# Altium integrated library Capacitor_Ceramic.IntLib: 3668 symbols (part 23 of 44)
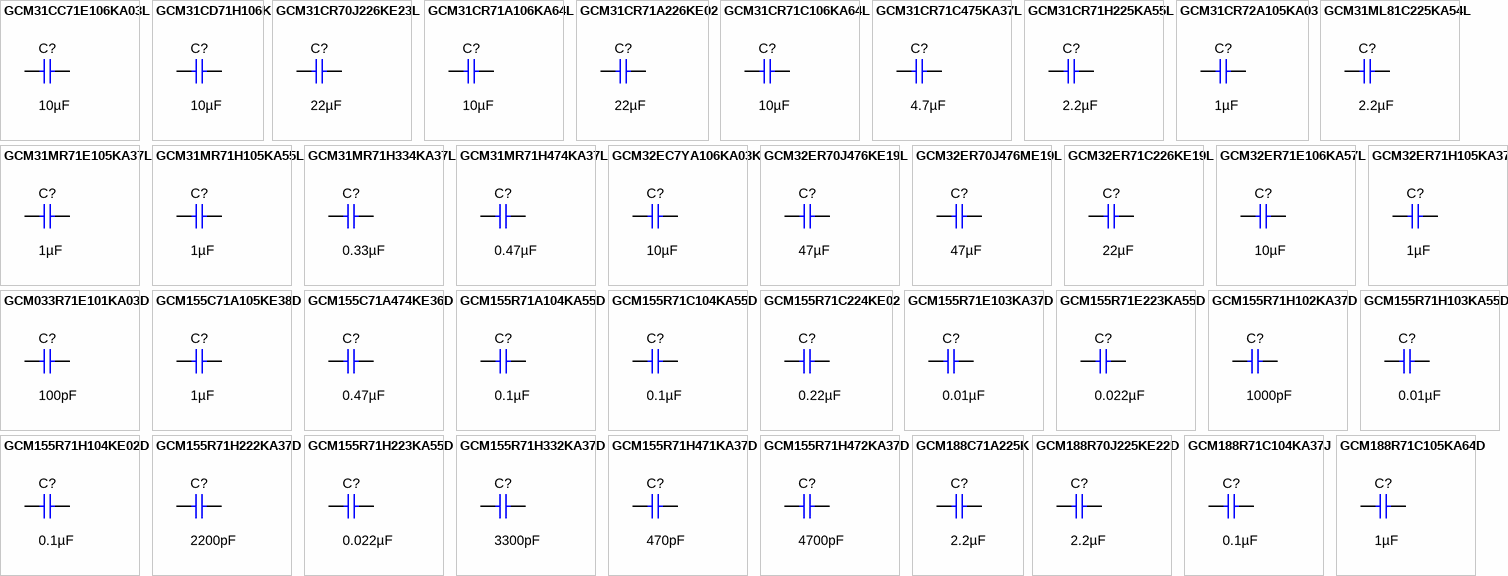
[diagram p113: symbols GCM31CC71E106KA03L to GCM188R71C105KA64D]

## GCM32ER70J476KE19L
designator C?  ValueDisplayed: 47µF  (hidden comment: GCM32ER70J476KE19L)
CAP, CERM, 47 µF, 6.3 V,+/- 10%, X7R, AEC-Q200 Grade 1, 1210; Manufacturer: MuRata; Polarized: N; CompType: Capacitor; Value: 47uF; U/M: EA; Cap_F: 0.000047; Tolerance_%: 10; VDC_V: 6.3; Value2: 6.3V; TaMin_C: -55; TaMax_C: 125; Cap_Case: 1210; SizeArea_mm2: 8; SizeAreaWB_mm2: 14.7; SizeX_mm: 3.2; SizeY_mm: 2.5; SizeZ_mm: 2.7; AEC Category: Q200; AEC Qualified: Y; AEC Grade: 1; Green_Lifecycle: Active; Green_REACh: Passed
signal-integrity model Cap
simulation model Cap
footprint 1210_270
footprint 1210_270M
footprint 1210_270L
pins: 1, 2

## GCM32ER70J476ME19L
designator C?  ValueDisplayed: 47µF  (hidden comment: GCM32ER70J476ME19L)
CAP, CERM, 47 µF, 6.3 V,+/- 20%, X7R, 1210; Manufacturer: MuRata; Polarized: N; CompType: Capacitor; Value: 47uF; U/M: EA; Cap_F: 0.000047; Tolerance_%: 20; VDC_V: 6.3; Value2: 6.3V; TaMin_C: -55; TaMax_C: 125; Cap_Case: 1210; SizeArea_mm2: 8; SizeAreaWB_mm2: 14.7; SizeX_mm: 3.2; SizeY_mm: 2.5; SizeZ_mm: 2.8; AEC Category: Q200; Green_Lifecycle: Active; Green_REACh: Passed
signal-integrity model Cap
simulation model Cap
footprint 1210_280
pins: 1, 2

## GCM32ER71C226KE19L
designator C?  ValueDisplayed: 22µF  (hidden comment: GCM32ER71C226KE19L)
CAP, CERM, 22 µF, 16 V,+/- 10%, X7R, 1210; Manufacturer: MuRata; Polarized: N; CompType: Capacitor; Value: 22uF; U/M: EA; Cap_F: 0.000022; Tolerance_%: 10; VDC_V: 16; Value2: 16V; TaMin_C: -55; TaMax_C: 125; Cap_Case: 1210; SizeArea_mm2: 8; SizeAreaWB_mm2: 14.7; SizeX_mm: 3.2; SizeY_mm: 2.5; SizeZ_mm: 2.8; AEC Category: Q200; Green_Lifecycle: Active; Green_REACh: Passed
signal-integrity model Cap
simulation model Cap
footprint 1210_280
pins: 1, 2

## GCM32ER71E106KA57L
designator C?  ValueDisplayed: 10µF  (hidden comment: GCM32ER71E106KA57L)
CAP, CERM, 10 µF, 25 V,+/- 10%, X7R, AEC-Q200 Grade 1, 1210; Manufacturer: MuRata; Polarized: N; CompType: Capacitor; Value: 10uF; U/M: EA; Cap_F: 0.00001; Tolerance_%: 10; VDC_V: 25; Value2: 25V; TaMin_C: -55; TaMax_C: 125; Cap_Case: 1210; SizeArea_mm2: 8; SizeAreaWB_mm2: 14.7; SizeX_mm: 3.2; SizeY_mm: 2.5; SizeZ_mm: 2.8; AEC Category: Q200; AEC Qualified: Y; AEC Grade: 1; Green_Lifecycle: Active; Green_REACh: Passed
signal-integrity model Cap
simulation model Cap
footprint 1210_280
pins: 1, 2

## GCM32ER71H105KA37L
designator C?  ValueDisplayed: 1µF  (hidden comment: GCM32ER71H105KA37L)
CAP, CERM, 1 µF, 50 V,+/- 10%, X7R, AEC-Q200 Grade 1, 1210; Manufacturer: MuRata; Polarized: N; CompType: Capacitor; Value: 1uF; U/M: EA; Cap_F: 0.000001; Tolerance_%: 10; VDC_V: 50; Value2: 50V; TaMin_C: -55; TaMax_C: 125; Cap_Case: 1210; SizeArea_mm2: 8; SizeAreaWB_mm2: 14.7; SizeX_mm: 3.2; SizeY_mm: 2.5; SizeZ_mm: 2.8; AEC Category: Q200; AEC Qualified: Y; AEC Grade: 1
signal-integrity model Cap
simulation model Cap
footprint 1210_280
pins: 1, 2

## GCM033R71E101KA03D
designator C?  ValueDisplayed: 100pF  (hidden comment: GCM033R71E101KA03D)
CAP, CERM, 100 pF, 25 V,+/- 10%, X7R, AEC-Q200 Grade 1, 0201; Manufacturer: MuRata; Polarized: N; CompType: Capacitor; Value: 100pF; U/M: EA; Cap_F: 0.0000000001; Tolerance_%: 10; VDC_V: 25; Value2: 25V; TaMin_C: -55; TaMax_C: 125; Cap_Case: 0201; SizeArea_mm2: 0.18; SizeAreaWB_mm2: 2.08; SizeX_mm: 0.6; SizeY_mm: 0.3; SizeZ_mm: 0.33; AEC Category: Q200; AEC Qualified: Y; AEC Grade: 1
signal-integrity model Cap
simulation model Cap
footprint 0201_033
footprint 0201_033M
footprint 0201_033L
pins: 1, 2

## GCM155C71A105KE38D
designator C?  ValueDisplayed: 1µF  (hidden comment: GCM155C71A105KE38D)
CAP, CERM, 1 µF, 10 V,+/- 10%, X7S, AEC-Q200 Grade 1, 0402; Manufacturer: MuRata; Polarized: N; CompType: Capacitor; Value: 1uF; U/M: EA; Cap_F: 0.000001; Tolerance_%: 10; Value2: 10V; TaMin_C: -55; TaMax_C: 125; Cap_Case: 0402; SizeArea_mm2: 0.5; SizeAreaWB_mm2: 3; SizeX_mm: 1; SizeZ_mm: 0.7; AEC Category: Q200; AEC Qualified: Y
signal-integrity model Cap
simulation model Cap
footprint 0402_070
pins: 1, 2

## GCM155C71A474KE36D
designator C?  ValueDisplayed: 0.47µF  (hidden comment: GCM155C71A474KE36D)
CAP, CERM, 0.47 µF, 10 V,+/- 10%, X7S, 0402; Manufacturer: MuRata; Polarized: N; CompType: Capacitor; Value: 0.47uF; U/M: EA; Cap_F: 0.00000047; Tolerance_%: 10; Value2: 10V; TaMin_C: -55; TaMax_C: 125; Cap_Case: 0402; SizeArea_mm2: 0.5; SizeAreaWB_mm2: 3; SizeX_mm: 1; SizeZ_mm: 0.6; AEC Category: Q200
signal-integrity model Cap
simulation model Cap
footprint 0402
footprint 0402M
footprint 0402L
footprint 0402S
pins: 1, 2

## GCM155R71A104KA55D
designator C?  ValueDisplayed: 0.1µF  (hidden comment: GCM155R71A104KA55D)
CAP, CERM, 0.1 µF, 10 V,+/- 10%, X7R, AEC-Q200 Grade 1, 0402; Manufacturer: MuRata; Polarized: N; CompType: Capacitor; Value: 0.1uF; U/M: EA; Cap_F: 0.0000001; Tolerance_%: 10; Value2: 10V; TaMin_C: -55; TaMax_C: 125; Cap_Case: 0402; SizeArea_mm2: 0.5; SizeAreaWB_mm2: 3; SizeX_mm: 1; SizeZ_mm: 0.6; AEC Category: Q200; AEC Qualified: Y
signal-integrity model Cap
simulation model Cap
footprint 0402
footprint 0402M
footprint 0402L
footprint 0402S
pins: 1, 2

## GCM155R71C104KA55D
designator C?  ValueDisplayed: 0.1µF  (hidden comment: GCM155R71C104KA55D)
CAP, CERM, 0.1 µF, 16 V,+/- 10%, X7R, 0402; Manufacturer: MuRata; Polarized: N; CompType: Capacitor; Value: 0.1uF; U/M: EA; Cap_F: 0.0000001; Tolerance_%: 10; VDC_V: 16; Value2: 16V; TaMin_C: -55; TaMax_C: 125; Cap_Case: 0402; SizeArea_mm2: 0.5; SizeAreaWB_mm2: 3; SizeX_mm: 1; SizeZ_mm: 0.6; AEC Category: Q200; Green_Lifecycle: Active; Green_REACh: Passed
signal-integrity model Cap
simulation model Cap
footprint 0402
footprint 0402M
footprint 0402L
footprint 0402S
pins: 1, 2

## GCM155R71C224KE02
designator C?  ValueDisplayed: 0.22µF  (hidden comment: GCM155R71C224KE02)
CAP, CERM, 0.22 µF, 16 V,+/- 10%, X7R, AEC-Q200 Grade 1, 0603; Manufacturer: MuRata; Polarized: N; CompType: Capacitor; Value: 0.22uF; U/M: EA; Cap_F: 0.00000022; Tolerance_%: 10; VDC_V: 16; Value2: 16V; TaMin_C: -55; TaMax_C: 125; Cap_Case: 0603; SizeArea_mm2: 1.28; SizeAreaWB_mm2: 4.68; SizeX_mm: 1.6; SizeY_mm: 0.8; SizeZ_mm: 1; AEC Category: Q200; AEC Qualified: Y
signal-integrity model Cap
simulation model Cap
footprint 0603
footprint 0603M
footprint 0603L
footprint 0603_HV
footprint 0603S
pins: 1, 2

## GCM155R71E103KA37D
designator C?  ValueDisplayed: 0.01µF  (hidden comment: GCM155R71E103KA37D)
CAP, CERM, 0.01 µF, 25 V,+/- 10%, X7R, 0402; Manufacturer: MuRata; Polarized: N; CompType: Capacitor; Value: 0.01uF; U/M: EA; Cap_F: 0.00000001; Tolerance_%: 10; VDC_V: 25; Value2: 25V; TaMin_C: -55; TaMax_C: 125; Cap_Case: 0402; SizeArea_mm2: 0.5; SizeAreaWB_mm2: 3; SizeX_mm: 1; SizeZ_mm: 0.6; AEC Category: Q200; Green_Lifecycle: Active; Green_REACh: Passed
signal-integrity model Cap
simulation model Cap
footprint 0402
footprint 0402M
footprint 0402L
footprint 0402S
pins: 1, 2

## GCM155R71E223KA55D
designator C?  ValueDisplayed: 0.022µF  (hidden comment: GCM155R71E223KA55D)
CAP, CERM, 0.022 µF, 25 V,+/- 10%, X7R, AEC-Q200 Grade 1, 0402; Manufacturer: MuRata; Polarized: N; CompType: Capacitor; Value: 0.022uF; U/M: EA; Cap_F: 0.000000022; Tolerance_%: 10; VDC_V: 25; Value2: 25V; TaMin_C: -55; TaMax_C: 125; Cap_Case: 0402; SizeArea_mm2: 0.5; SizeAreaWB_mm2: 3; SizeX_mm: 1; SizeZ_mm: 0.6; AEC Category: Q200; AEC Qualified: Y
signal-integrity model Cap
simulation model Cap
footprint 0402
footprint 0402M
footprint 0402L
footprint 0402S
pins: 1, 2

## GCM155R71H102KA37D
designator C?  ValueDisplayed: 1000pF  (hidden comment: GCM155R71H102KA37D)
CAP, CERM, 1000 pF, 50 V,+/- 10%, X7R, AEC-Q200 Grade 1, 0402; Manufacturer: MuRata; Polarized: N; CompType: Capacitor; Value: 1000pF; U/M: EA; Cap_F: 0.000000001; Tolerance_%: 10; VDC_V: 50; Value2: 50V; TaMin_C: -55; TaMax_C: 125; Cap_Case: 0402; SizeArea_mm2: 0.5; SizeAreaWB_mm2: 3; SizeX_mm: 1; SizeZ_mm: 0.6; AEC Category: Q200; AEC Qualified: Y
signal-integrity model Cap
simulation model Cap
footprint 0402
footprint 0402M
footprint 0402L
footprint 0402S
pins: 1, 2

## GCM155R71H103KA55D
designator C?  ValueDisplayed: 0.01µF  (hidden comment: GCM155R71H103KA55D)
CAP, CERM, 0.01 µF, 50 V,+/- 10%, X7R, AEC-Q200 Grade 1, 0402; Manufacturer: MuRata; Polarized: N; CompType: Capacitor; Value: 0.01uF; U/M: EA; Cap_F: 0.00000001; Tolerance_%: 10; VDC_V: 50; Value2: 50V; TaMin_C: -55; TaMax_C: 125; Cap_Case: 0402; SizeArea_mm2: 0.5; SizeAreaWB_mm2: 3; SizeX_mm: 1; SizeZ_mm: 0.6; AEC Category: Q200; AEC Qualified: Y; Green_Lifecycle: Active; Green_REACh: Passed
signal-integrity model Cap
simulation model Cap
footprint 0402
footprint 0402M
footprint 0402L
footprint 0402S
pins: 1, 2

## GCM155R71H104KE02D
designator C?  ValueDisplayed: 0.1µF  (hidden comment: GCM155R71H104KE02D)
CAP, CERM, 0.1 µF, 50 V,+/- 10%, X7R, AEC-Q200 Grade 1, 0402; Manufacturer: MuRata; Polarized: N; CompType: Capacitor; Value: 0.1uF; U/M: EA; Cap_F: 0.0000001; Tolerance_%: 10; VDC_V: 50; Value2: 50V; TaMin_C: -55; TaMax_C: 125; Cap_Case: 0402; SizeArea_mm2: 0.5; SizeAreaWB_mm2: 3; SizeX_mm: 1; SizeZ_mm: 0.6; AEC Category: Q200; AEC Qualified: Y
signal-integrity model Cap
simulation model Cap
footprint 0402
footprint 0402M
footprint 0402L
footprint 0402S
pins: 1, 2

## GCM155R71H222KA37D
designator C?  ValueDisplayed: 2200pF  (hidden comment: GCM155R71H222KA37D)
CAP, CERM, 2200 pF, 50 V,+/- 10%, X7R, AEC-Q200 Grade 1, 0402; Manufacturer: MuRata; Polarized: N; CompType: Capacitor; Value: 2200pF; U/M: EA; Cap_F: 0.0000000022; Tolerance_%: 10; VDC_V: 50; Value2: 50V; TaMin_C: -55; TaMax_C: 125; Cap_Case: 0402; SizeArea_mm2: 0.5; SizeAreaWB_mm2: 3; SizeX_mm: 1; SizeZ_mm: 0.6; AEC Category: Q200; AEC Qualified: Y
signal-integrity model Cap
simulation model Cap
footprint 0402
footprint 0402M
footprint 0402L
footprint 0402S
pins: 1, 2

## GCM155R71H223KA55D
designator C?  ValueDisplayed: 0.022µF  (hidden comment: GCM155R71H223KA55D)
CAP, CERM, 0.022 µF, 50 V,+/- 10%, C0G/NP0, 0402; Manufacturer: MuRata; Polarized: N; CompType: Capacitor; Value: 0.022uF; U/M: EA; Cap_F: 0.000000022; Tolerance_%: 10; VDC_V: 50; Value2: 50V; TaMin_C: -55; TaMax_C: 125; Cap_Case: 0402; SizeArea_mm2: 0.5; SizeAreaWB_mm2: 3; SizeX_mm: 1; SizeZ_mm: 0.6; AEC Category: Q200
signal-integrity model Cap
simulation model Cap
footprint 0402
footprint 0402M
footprint 0402L
footprint 0402S
pins: 1, 2

## GCM155R71H332KA37D
designator C?  ValueDisplayed: 3300pF  (hidden comment: GCM155R71H332KA37D)
CAP, CERM, 3300 pF, 50 V,+/- 10%, X7R, AEC-Q200 Grade 1, 0402; Manufacturer: MuRata; Polarized: N; CompType: Capacitor; Value: 3300pF; U/M: EA; Cap_F: 0.0000000033; Tolerance_%: 10; VDC_V: 50; Value2: 50V; TaMin_C: -55; TaMax_C: 125; Cap_Case: 0402; SizeArea_mm2: 0.5; SizeAreaWB_mm2: 3; SizeX_mm: 1; SizeZ_mm: 0.6; AEC Category: Q200; AEC Qualified: Y
signal-integrity model Cap
simulation model Cap
footprint 0402
footprint 0402M
footprint 0402L
footprint 0402S
pins: 1, 2

## GCM155R71H471KA37D
designator C?  ValueDisplayed: 470pF  (hidden comment: GCM155R71H471KA37D)
CAP, CERM, 470 pF, 50 V,+/- 10%, X7R, AEC-Q200 Grade 1, 0402; Manufacturer: MuRata; Polarized: N; CompType: Capacitor; Value: 470pF; U/M: EA; Cap_F: 0.00000000047; Tolerance_%: 10; VDC_V: 50; Value2: 50V; TaMin_C: -55; TaMax_C: 125; Cap_Case: 0402; SizeArea_mm2: 0.5; SizeAreaWB_mm2: 3; SizeX_mm: 1; SizeZ_mm: 0.6; AEC Category: Q200; AEC Qualified: Y
signal-integrity model Cap
simulation model Cap
footprint 0402
footprint 0402M
footprint 0402L
footprint 0402S
pins: 1, 2

## GCM155R71H472KA37D
designator C?  ValueDisplayed: 4700pF  (hidden comment: GCM155R71H472KA37D)
CAP, CERM, 4700 pF, 50 V,+/- 10%, X7R, AEC-Q200 Grade 1, 0402; Manufacturer: MuRata; Polarized: N; CompType: Capacitor; Value: 4700pF; U/M: EA; Cap_F: 0.0000000047; Tolerance_%: 10; VDC_V: 50; Value2: 50V; TaMin_C: -55; TaMax_C: 125; Cap_Case: 0402; SizeArea_mm2: 0.5; SizeAreaWB_mm2: 3; SizeX_mm: 1; SizeZ_mm: 0.6; AEC Category: Q200; AEC Qualified: Y
signal-integrity model Cap
simulation model Cap
footprint 0402
footprint 0402M
footprint 0402L
footprint 0402S
pins: 1, 2

## GCM188C71A225K
designator C?  ValueDisplayed: 2.2µF  (hidden comment: GCM188C71A225K)
CAP, CERM, 2.2 µF, 10 V,+/- 10%, X7S, 0603; Manufacturer: MuRata; Polarized: N; CompType: Capacitor; Value: 2.2uF; U/M: EA; Cap_F: 0.0000022; Tolerance_%: 10; Value2: 10V; TaMin_C: -55; TaMax_C: 125; Cap_Case: 0603; SizeArea_mm2: 1.28; SizeAreaWB_mm2: 4.68; SizeX_mm: 1.6; SizeY_mm: 0.8; SizeZ_mm: 1; AEC Category: Q200
signal-integrity model Cap
simulation model Cap
footprint 0603
footprint 0603M
footprint 0603L
footprint 0603_HV
footprint 0603S
pins: 1, 2

## GCM188R70J225KE22D
designator C?  ValueDisplayed: 2.2µF  (hidden comment: GCM188R70J225KE22D)
CAP, CERM, 2.2 µF, 6.3 V,+/- 10%, X7R, AEC-Q200 Grade 1, 0603; Manufacturer: MuRata; Polarized: N; CompType: Capacitor; Value: 2.2uF; U/M: EA; Cap_F: 0.0000022; Tolerance_%: 10; VDC_V: 6.3; Value2: 6.3V; TaMin_C: -55; TaMax_C: 125; Cap_Case: 0603; SizeArea_mm2: 1.28; SizeAreaWB_mm2: 4.68; SizeX_mm: 1.6; SizeY_mm: 0.8; SizeZ_mm: 1; AEC Category: Q200; AEC Qualified: Y; Green_Lifecycle: Active; Green_REACh: Passed
signal-integrity model Cap
simulation model Cap
footprint 0603
footprint 0603M
footprint 0603L
footprint 0603_HV
footprint 0603S
pins: 1, 2

## GCM188R71C104KA37J
designator C?  ValueDisplayed: 0.1µF  (hidden comment: GCM188R71C104KA37J)
CAP, CERM, 0.1 µF, 16 V,+/- 10%, X7R, AEC-Q200 Grade 1, 0603; Manufacturer: MuRata; Polarized: N; CompType: Capacitor; Value: 0.1uF; U/M: EA; Cap_F: 0.0000001; Tolerance_%: 10; VDC_V: 16; Value2: 16V; TaMin_C: -55; TaMax_C: 125; Cap_Case: 0603; SizeArea_mm2: 1.28; SizeAreaWB_mm2: 4.68; SizeX_mm: 1.6; SizeY_mm: 0.8; SizeZ_mm: 1; AEC Category: Q200; AEC Qualified: Y; Green_Lifecycle: Active; Green_REACh: Passed
signal-integrity model Cap
simulation model Cap
footprint 0603
footprint 0603M
footprint 0603L
footprint 0603_HV
footprint 0603S
pins: 1, 2

## GCM188R71C105KA64D
designator C?  ValueDisplayed: 1µF  (hidden comment: GCM188R71C105KA64D)
CAP, CERM, 1 µF, 16 V,+/- 10%, X7R, AEC-Q200 Grade 1, 0603; Manufacturer: MuRata; Polarized: N; CompType: Capacitor; Value: 1uF; U/M: EA; Cap_F: 0.000001; Tolerance_%: 10; VDC_V: 16; Value2: 16V; TaMin_C: -55; TaMax_C: 125; Cap_Case: 0603; SizeArea_mm2: 1.28; SizeAreaWB_mm2: 4.68; SizeX_mm: 1.6; SizeY_mm: 0.8; SizeZ_mm: 1; AEC Category: Q200; AEC Qualified: Y; Green_Lifecycle: Active; Green_REACh: Passed
signal-integrity model Cap
simulation model Cap
footprint 0603
footprint 0603M
footprint 0603L
footprint 0603_HV
footprint 0603S
pins: 1, 2

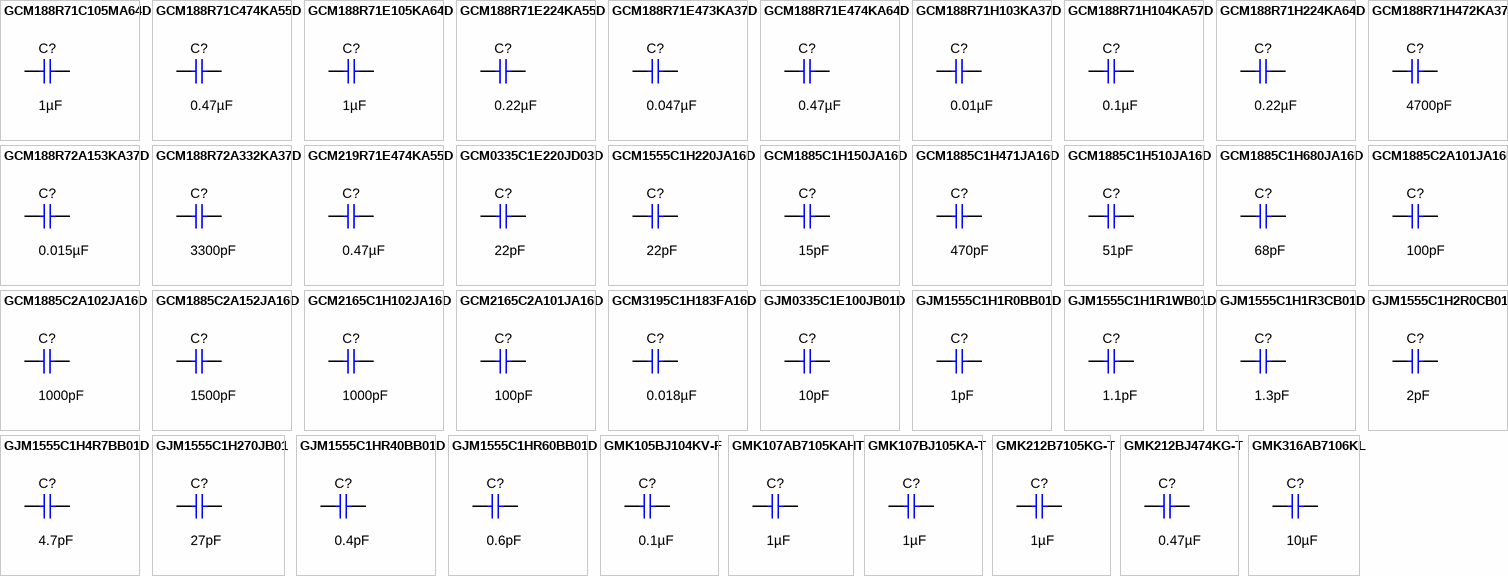
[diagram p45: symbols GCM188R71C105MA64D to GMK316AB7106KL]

## GCM188R71C105MA64D
designator C?  ValueDisplayed: 1µF  (hidden comment: GCM188R71C105MA64D)
CAP, CERM, 1 µF, 16 V,+/- 20%, X7R, AEC-Q200 Grade 1, 0603; Manufacturer: MuRata; Polarized: N; CompType: Capacitor; Value: 1uF; U/M: EA; Cap_F: 0.000001; Tolerance_%: 20; VDC_V: 16; Value2: 16V; TaMin_C: -55; TaMax_C: 125; Cap_Case: 0603; SizeArea_mm2: 1.28; SizeAreaWB_mm2: 4.68; SizeX_mm: 1.6; SizeY_mm: 0.8; SizeZ_mm: 1; AEC Category: Q200; AEC Qualified: Y
signal-integrity model Cap
simulation model Cap
footprint 0603
footprint 0603M
footprint 0603L
footprint 0603_HV
footprint 0603S
pins: 1, 2

## GCM188R71C474KA55D
designator C?  ValueDisplayed: 0.47µF  (hidden comment: GCM188R71C474KA55D)
CAP, CERM, 0.47 µF, 16 V,+/- 10%, X7R, AEC-Q200 Grade 1, 0603; Manufacturer: MuRata; Polarized: N; CompType: Capacitor; Value: 0.47uF; U/M: EA; Cap_F: 0.00000047; Tolerance_%: 10; VDC_V: 16; Value2: 16V; TaMin_C: -55; TaMax_C: 125; Cap_Case: 0603; SizeArea_mm2: 1.28; SizeAreaWB_mm2: 4.68; SizeX_mm: 1.6; SizeY_mm: 0.8; SizeZ_mm: 1; AEC Category: Q200; AEC Qualified: Y
signal-integrity model Cap
simulation model Cap
footprint 0603
footprint 0603M
footprint 0603L
footprint 0603_HV
footprint 0603S
pins: 1, 2

## GCM188R71E105KA64D
designator C?  ValueDisplayed: 1µF  (hidden comment: GCM188R71E105KA64D)
CAP, CERM, 1 µF, 25 V,+/- 10%, X7R, AEC-Q200 Grade 1, 0603; Manufacturer: MuRata; Polarized: N; CompType: Capacitor; Value: 1uF; U/M: EA; Cap_F: 0.000001; Tolerance_%: 10; VDC_V: 25; Value2: 25V; TaMin_C: -55; TaMax_C: 125; Cap_Case: 0603; SizeArea_mm2: 1.28; SizeAreaWB_mm2: 4.68; SizeX_mm: 1.6; SizeY_mm: 0.8; SizeZ_mm: 1; AEC Category: Q200; AEC Qualified: Y
signal-integrity model Cap
simulation model Cap
footprint 0603
footprint 0603M
footprint 0603L
footprint 0603_HV
footprint 0603S
pins: 1, 2

## GCM188R71E224KA55D
designator C?  ValueDisplayed: 0.22µF  (hidden comment: GCM188R71E224KA55D)
CAP, CERM, 0.22 µF, 25 V,+/- 10%, X7R, AEC-Q200 Grade 1, 0603; Manufacturer: MuRata; Polarized: N; CompType: Capacitor; Value: 0.22uF; U/M: EA; Cap_F: 0.00000022; Tolerance_%: 10; VDC_V: 25; Value2: 25V; TaMin_C: -55; TaMax_C: 125; Cap_Case: 0603; SizeArea_mm2: 1.28; SizeAreaWB_mm2: 4.68; SizeX_mm: 1.6; SizeY_mm: 0.8; SizeZ_mm: 1; AEC Category: Q200; AEC Qualified: Y
signal-integrity model Cap
simulation model Cap
footprint 0603
footprint 0603M
footprint 0603L
footprint 0603_HV
footprint 0603S
pins: 1, 2

## GCM188R71E473KA37D
designator C?  ValueDisplayed: 0.047µF  (hidden comment: GCM188R71E473KA37D)
CAP, CERM, 0.047 µF, 25 V,+/- 10%, X7R, AEC-Q200 Grade 1, 0603; Manufacturer: MuRata; Polarized: N; CompType: Capacitor; Value: 0.047uF; U/M: EA; Cap_F: 0.000000047; Tolerance_%: 10; VDC_V: 25; Value2: 25V; TaMin_C: -55; TaMax_C: 125; Cap_Case: 0603; SizeArea_mm2: 1.28; SizeAreaWB_mm2: 4.68; SizeX_mm: 1.6; SizeY_mm: 0.8; SizeZ_mm: 1; AEC Category: Q200; AEC Qualified: Y
signal-integrity model Cap
simulation model Cap
footprint 0603
footprint 0603M
footprint 0603L
footprint 0603_HV
footprint 0603S
pins: 1, 2

## GCM188R71E474KA64D
designator C?  ValueDisplayed: 0.47µF  (hidden comment: GCM188R71E474KA64D)
CAP, CERM, 0.47 µF, 25 V,+/- 10%, X7R, AEC-Q200 Grade 1, 0603; Manufacturer: MuRata; Polarized: N; CompType: Capacitor; Value: 0.47uF; U/M: EA; Cap_F: 0.00000047; Tolerance_%: 10; VDC_V: 25; Value2: 25V; TaMin_C: -55; TaMax_C: 125; Cap_Case: 0603; SizeArea_mm2: 1.28; SizeAreaWB_mm2: 4.68; SizeX_mm: 1.6; SizeY_mm: 0.8; SizeZ_mm: 1; AEC Category: Q200; AEC Qualified: Y
signal-integrity model Cap
simulation model Cap
footprint 0603
footprint 0603M
footprint 0603L
footprint 0603_HV
footprint 0603S
pins: 1, 2

## GCM188R71H103KA37D
designator C?  ValueDisplayed: 0.01µF  (hidden comment: GCM188R71H103KA37D)
CAP, CERM, 0.01 µF, 50 V,+/- 10%, X7R, AEC-Q200 Grade 1, 0603; Manufacturer: MuRata; Polarized: N; CompType: Capacitor; Value: 0.01uF; U/M: EA; Cap_F: 0.00000001; Tolerance_%: 10; VDC_V: 50; Value2: 50V; TaMin_C: -55; TaMax_C: 125; Cap_Case: 0603; SizeArea_mm2: 1.28; SizeAreaWB_mm2: 4.68; SizeX_mm: 1.6; SizeY_mm: 0.8; SizeZ_mm: 1; AEC Category: Q200; AEC Qualified: Y
signal-integrity model Cap
simulation model Cap
footprint 0603
footprint 0603M
footprint 0603L
footprint 0603_HV
footprint 0603S
pins: 1, 2

## GCM188R71H104KA57D
designator C?  ValueDisplayed: 0.1µF  (hidden comment: GCM188R71H104KA57D)
CAP, CERM, 0.1 µF, 50 V,+/- 10%, X7R, 0603; Manufacturer: MuRata; Polarized: N; CompType: Capacitor; Value: 0.1uF; U/M: EA; Cap_F: 0.0000001; Tolerance_%: 10; ESR_ohm: 0.02; Value1: 0.02 ohm; VDC_V: 50; Value2: 50V; IRMS_A: 1.84; TaMin_C: -55; TaMax_C: 125; Cap_Case: 0603; SizeArea_mm2: 1.28; SizeAreaWB_mm2: 4.68; SizeX_mm: 1.6; SizeY_mm: 0.8; SizeZ_mm: 1; AEC Category: Q200; Green_Lifecycle: Active; Green_REACh: Passed
signal-integrity model Cap
simulation model Cap
footprint 0603
footprint 0603M
footprint 0603L
footprint 0603_HV
footprint 0603S
pins: 1, 2

## GCM188R71H224KA64D
designator C?  ValueDisplayed: 0.22µF  (hidden comment: GCM188R71H224KA64D)
CAP, CERM, 0.22 µF, 50 V,+/- 10%, X7R, AEC-Q200 Grade 1, 0603; Manufacturer: MuRata; Polarized: N; CompType: Capacitor; Value: 0.22uF; U/M: EA; Cap_F: 0.00000022; Tolerance_%: 10; VDC_V: 50; Value2: 50V; TaMin_C: -55; TaMax_C: 125; Cap_Case: 0603; SizeArea_mm2: 1.28; SizeAreaWB_mm2: 4.68; SizeX_mm: 1.6; SizeY_mm: 0.8; SizeZ_mm: 1; AEC Category: Q200; AEC Qualified: Y; Green_Lifecycle: Active; Green_REACh: Passed
signal-integrity model Cap
simulation model Cap
footprint 0603
footprint 0603M
footprint 0603L
footprint 0603_HV
footprint 0603S
pins: 1, 2

## GCM188R71H472KA37D
designator C?  ValueDisplayed: 4700pF  (hidden comment: GCM188R71H472KA37D)
CAP, CERM, 4700 pF, 50 V,+/- 10%, X7R, AEC-Q200 Grade 1, 0603; Manufacturer: MuRata; Polarized: N; CompType: Capacitor; Value: 4700pF; U/M: EA; Cap_F: 0.0000000047; Tolerance_%: 10; VDC_V: 50; Value2: 50V; TaMin_C: -55; TaMax_C: 125; Cap_Case: 0603; SizeArea_mm2: 1.28; SizeAreaWB_mm2: 4.68; SizeX_mm: 1.6; SizeY_mm: 0.8; SizeZ_mm: 1; AEC Category: Q200; AEC Qualified: Y
signal-integrity model Cap
simulation model Cap
footprint 0603
footprint 0603M
footprint 0603L
footprint 0603_HV
footprint 0603S
pins: 1, 2

## GCM188R72A153KA37D
designator C?  ValueDisplayed: 0.015µF  (hidden comment: GCM188R72A153KA37D)
CAP, CERM, 0.015 µF, 100 V,+/- 10%, X7R, AEC-Q200 Grade 1, 0603; Manufacturer: MuRata; Polarized: N; CompType: Capacitor; Value: 0.015uF; U/M: EA; Cap_F: 0.000000015; Tolerance_%: 10; VDC_V: 100; Value2: 100V; TaMin_C: -55; TaMax_C: 125; Cap_Case: 0603; SizeArea_mm2: 1.28; SizeAreaWB_mm2: 4.68; SizeX_mm: 1.6; SizeY_mm: 0.8; SizeZ_mm: 1; AEC Category: Q200; AEC Qualified: Y
signal-integrity model Cap
simulation model Cap
footprint 0603
footprint 0603M
footprint 0603L
footprint 0603_HV
footprint 0603S
pins: 1, 2

## GCM188R72A332KA37D
designator C?  ValueDisplayed: 3300pF  (hidden comment: GCM188R72A332KA37D)
CAP, CERM, 3300 pF, 100 V,+/- 10%, X7R, AEC-Q200 Grade 1, 0603; Manufacturer: MuRata; Polarized: N; CompType: Capacitor; Value: 3300pF; U/M: EA; Cap_F: 0.0000000033; Tolerance_%: 10; VDC_V: 100; Value2: 100V; TaMin_C: -55; TaMax_C: 125; Cap_Case: 0603; SizeArea_mm2: 1.28; SizeAreaWB_mm2: 4.68; SizeX_mm: 1.6; SizeY_mm: 0.8; SizeZ_mm: 1; AEC Category: Q200; AEC Qualified: Y
signal-integrity model Cap
simulation model Cap
footprint 0603
footprint 0603M
footprint 0603L
footprint 0603_HV
footprint 0603S
pins: 1, 2

## GCM219R71E474KA55D
designator C?  ValueDisplayed: 0.47µF  (hidden comment: GCM219R71E474KA55D)
CAP, CERM, 0.47 µF, 25 V,+/- 10%, X7R, AEC-Q200 Grade 1, 0805; Manufacturer: MuRata; Polarized: N; CompType: Capacitor; Value: 0.47uF; U/M: EA; Cap_F: 0.00000047; Tolerance_%: 10; VDC_V: 25; Value2: 25V; TaMin_C: -55; TaMax_C: 125; Cap_Case: 0805; SizeArea_mm2: 2.5; SizeAreaWB_mm2: 6.75; SizeX_mm: 2; SizeY_mm: 1.25; SizeZ_mm: 1.45; AEC Category: Q200; AEC Qualified: Y; AEC Grade: 1
signal-integrity model Cap
simulation model Cap
footprint 0805_HV
footprint 0805_HV1
footprint 0805
footprint 0805M
footprint 0805L
pins: 1, 2

## GCM0335C1E220JD03D
designator C?  ValueDisplayed: 22pF  (hidden comment: GCM0335C1E220JD03D)
CAP, CERM, 22 pF, 25 V,+/- 5%, C0G/NP0, AEC-Q200 Grade 1, 0201; Manufacturer: MuRata; Polarized: N; CompType: Capacitor; Value: 22pF; U/M: EA; Cap_F: 0.000000000022; Tolerance_%: 5; VDC_V: 25; Value2: 25V; TaMin_C: -55; TaMax_C: 125; Cap_Case: 0201; SizeArea_mm2: 0.18; SizeAreaWB_mm2: 2.08; SizeX_mm: 0.6; SizeY_mm: 0.3; SizeZ_mm: 0.33; AEC Category: Q200; AEC Qualified: Y; AEC Grade: 1
signal-integrity model Cap
simulation model Cap
footprint 0201_033
footprint 0201_033M
footprint 0201_033L
pins: 1, 2

## GCM1555C1H220JA16D
designator C?  ValueDisplayed: 22pF  (hidden comment: GCM1555C1H220JA16D)
CAP, CERM, 22 pF, 50 V,+/- 5%, C0G/NP0, AEC-Q200 Grade 1, 0402; Manufacturer: MuRata; Polarized: N; CompType: Capacitor; Value: 22pF; U/M: EA; Cap_F: 0.000000000022; Tolerance_%: 5; VDC_V: 50; Value2: 50V; TaMin_C: -55; TaMax_C: 125; Cap_Case: 0402; SizeArea_mm2: 0.5; SizeAreaWB_mm2: 3; SizeX_mm: 1; SizeZ_mm: 0.6; AEC Category: Q200; AEC Qualified: Y
signal-integrity model Cap
simulation model Cap
footprint 0402
footprint 0402M
footprint 0402L
footprint 0402S
pins: 1, 2

## GCM1885C1H150JA16D
designator C?  ValueDisplayed: 15pF  (hidden comment: GCM1885C1H150JA16D)
CAP, CERM, 15 pF, 50 V,+/- 5%, C0G/NP0, AEC-Q200 Grade 1, 0603; Manufacturer: MuRata; Polarized: N; CompType: Capacitor; Value: 15pF; U/M: EA; Cap_F: 0.000000000015; Tolerance_%: 5; VDC_V: 50; Value2: 50V; TaMin_C: -55; TaMax_C: 125; Cap_Case: 0603; SizeArea_mm2: 1.28; SizeAreaWB_mm2: 4.68; SizeX_mm: 1.6; SizeY_mm: 0.8; SizeZ_mm: 1; AEC Category: Q200; AEC Qualified: Y
signal-integrity model Cap
simulation model Cap
footprint 0603
footprint 0603M
footprint 0603L
footprint 0603_HV
footprint 0603S
pins: 1, 2

## GCM1885C1H471JA16D
designator C?  ValueDisplayed: 470pF  (hidden comment: GCM1885C1H471JA16D)
CAP, CERM, 470 pF, 50 V,+/- 5%, C0G/NP0, AEC-Q200 Grade 1, 0603; Manufacturer: MuRata; Polarized: N; CompType: Capacitor; Value: 470pF; U/M: EA; Cap_F: 0.00000000047; Tolerance_%: 5; VDC_V: 50; Value2: 50V; TaMin_C: -55; TaMax_C: 125; Cap_Case: 0603; SizeArea_mm2: 1.28; SizeAreaWB_mm2: 4.68; SizeX_mm: 1.6; SizeY_mm: 0.8; SizeZ_mm: 1; AEC Category: Q200; AEC Qualified: Y; Green_Lifecycle: Active; Green_REACh: Passed
signal-integrity model Cap
simulation model Cap
footprint 0603
footprint 0603M
footprint 0603L
footprint 0603_HV
footprint 0603S
pins: 1, 2

## GCM1885C1H510JA16D
designator C?  ValueDisplayed: 51pF  (hidden comment: GCM1885C1H510JA16D)
CAP, CERM, 51 pF, 50 V,+/- 5%, C0G/NP0, AEC-Q200 Grade 1, 0603; Manufacturer: MuRata; Polarized: N; CompType: Capacitor; Value: 51pF; U/M: EA; Cap_F: 0.000000000051; Tolerance_%: 5; VDC_V: 50; Value2: 50V; TaMin_C: -55; TaMax_C: 125; Cap_Case: 0603; SizeArea_mm2: 1.28; SizeAreaWB_mm2: 4.68; SizeX_mm: 1.6; SizeY_mm: 0.8; SizeZ_mm: 1; AEC Category: Q200; AEC Qualified: Y
signal-integrity model Cap
simulation model Cap
footprint 0603
footprint 0603M
footprint 0603L
footprint 0603_HV
footprint 0603S
pins: 1, 2

## GCM1885C1H680JA16D
designator C?  ValueDisplayed: 68pF  (hidden comment: GCM1885C1H680JA16D)
CAP, CERM, 68 pF, 50 V,+/- 5%, C0G/NP0, AEC-Q200 Grade 1, 0603; Manufacturer: MuRata; Polarized: N; CompType: Capacitor; Value: 68pF; U/M: EA; Cap_F: 0.000000000068; Tolerance_%: 5; VDC_V: 50; Value2: 50V; TaMin_C: -55; TaMax_C: 125; Cap_Case: 0603; SizeArea_mm2: 1.28; SizeAreaWB_mm2: 4.68; SizeX_mm: 1.6; SizeY_mm: 0.8; SizeZ_mm: 1; AEC Category: Q200; AEC Qualified: Y
signal-integrity model Cap
simulation model Cap
footprint 0603
footprint 0603M
footprint 0603L
footprint 0603_HV
footprint 0603S
pins: 1, 2

## GCM1885C2A101JA16D
designator C?  ValueDisplayed: 100pF  (hidden comment: GCM1885C2A101JA16D)
CAP, CERM, 100 pF, 100 V,+/- 5%, C0G/NP0, AEC-Q200 Grade 1, 0603; Manufacturer: MuRata; Polarized: N; CompType: Capacitor; Value: 100pF; U/M: EA; Cap_F: 0.0000000001; Tolerance_%: 5; VDC_V: 100; Value2: 100V; TaMin_C: -55; TaMax_C: 125; Cap_Case: 0603; SizeArea_mm2: 1.28; SizeAreaWB_mm2: 4.68; SizeX_mm: 1.6; SizeY_mm: 0.8; SizeZ_mm: 1; AEC Category: Q200; AEC Qualified: Y
signal-integrity model Cap
simulation model Cap
footprint 0603
footprint 0603M
footprint 0603L
footprint 0603_HV
footprint 0603S
pins: 1, 2

## GCM1885C2A102JA16D
designator C?  ValueDisplayed: 1000pF  (hidden comment: GCM1885C2A102JA16D)
CAP, CERM, 1000 pF, 100 V,+/- 5%, C0G/NP0, AEC-Q200 Grade 1, 0603; Manufacturer: MuRata; Polarized: N; CompType: Capacitor; Value: 1000pF; U/M: EA; Cap_F: 0.000000001; Tolerance_%: 5; VDC_V: 100; Value2: 100V; TaMin_C: -55; TaMax_C: 125; Cap_Case: 0603; SizeArea_mm2: 1.28; SizeAreaWB_mm2: 4.68; SizeX_mm: 1.6; SizeY_mm: 0.8; SizeZ_mm: 1; AEC Category: Q200; AEC Qualified: Y
signal-integrity model Cap
simulation model Cap
footprint 0603
footprint 0603M
footprint 0603L
footprint 0603_HV
footprint 0603S
pins: 1, 2

## GCM1885C2A152JA16D
designator C?  ValueDisplayed: 1500pF  (hidden comment: GCM1885C2A152JA16D)
CAP, CERM, 1500 pF, 100 V,+/- 5%, C0G/NP0, AEC-Q200 Grade 1, 0603; Manufacturer: MuRata; Polarized: N; CompType: Capacitor; Value: 1500pF; U/M: EA; Cap_F: 0.0000000015; Tolerance_%: 5; VDC_V: 100; Value2: 100V; TaMin_C: -55; TaMax_C: 125; Cap_Case: 0603; SizeArea_mm2: 1.28; SizeAreaWB_mm2: 4.68; SizeX_mm: 1.6; SizeY_mm: 0.8; SizeZ_mm: 1; AEC Category: Q200; AEC Qualified: Y
signal-integrity model Cap
simulation model Cap
footprint 0603
footprint 0603M
footprint 0603L
footprint 0603_HV
footprint 0603S
pins: 1, 2

## GCM2165C1H102JA16D
designator C?  ValueDisplayed: 1000pF  (hidden comment: GCM2165C1H102JA16D)
CAP, CERM, 1000 pF, 50 V,+/- 5%, C0G/NP0, AEC-Q200 Grade 1, 0805; Manufacturer: MuRata; Polarized: N; CompType: Capacitor; Value: 1000pF; U/M: EA; Cap_F: 0.000000001; Tolerance_%: 5; VDC_V: 50; Value2: 50V; TaMin_C: -55; TaMax_C: 125; Cap_Case: 0805; SizeArea_mm2: 2.5; SizeAreaWB_mm2: 6.75; SizeX_mm: 2; SizeY_mm: 1.25; SizeZ_mm: 1.45; AEC Category: Q200; AEC Qualified: Y; AEC Grade: 1
signal-integrity model Cap
simulation model Cap
footprint 0805_HV
footprint 0805_HV1
footprint 0805
footprint 0805M
footprint 0805L
pins: 1, 2

## GCM2165C2A101JA16D
designator C?  ValueDisplayed: 100pF  (hidden comment: GCM2165C2A101JA16D)
CAP, CERM, 100 pF, 100 V,+/- 5%, C0G/NP0, AEC-Q200 Grade 1, 0805; Manufacturer: MuRata; Polarized: N; CompType: Capacitor; Value: 100pF; U/M: EA; Cap_F: 0.0000000001; Tolerance_%: 5; VDC_V: 100; Value2: 100V; TaMin_C: -55; TaMax_C: 105; Cap_Case: 0805; SizeArea_mm2: 2.5; SizeAreaWB_mm2: 6.75; SizeX_mm: 2; SizeY_mm: 1.25; SizeZ_mm: 1.45; AEC Category: Q200; AEC Qualified: Y; AEC Grade: 1
signal-integrity model Cap
simulation model Cap
footprint 0805_HV
footprint 0805_HV1
footprint 0805
footprint 0805M
footprint 0805L
pins: 1, 2

## GCM3195C1H183FA16D
designator C?  ValueDisplayed: 0.018µF  (hidden comment: GCM3195C1H183FA16D)
CAP, CERM, 0.018 µF, 50 V,+/- 1%, C0G/NP0, AEC-Q200 Grade 1, 1206; Manufacturer: MuRata; Polarized: N; CompType: Capacitor; Value: 0.018uF; U/M: EA; Cap_F: 0.000000018; Tolerance_%: 1; VDC_V: 50; Value2: 50V; TaMin_C: -55; TaMax_C: 125; Cap_Case: 1206; SizeArea_mm2: 5.12; SizeAreaWB_mm2: 10.92; SizeX_mm: 3.2; SizeY_mm: 1.6; SizeZ_mm: 1.35; AEC Category: Q200; AEC Qualified: Y
signal-integrity model Cap
simulation model Cap
footprint 1206
footprint 1206M
footprint 1206L
pins: 1, 2

## GJM0335C1E100JB01D
designator C?  ValueDisplayed: 10pF  (hidden comment: GJM0335C1E100JB01D)
CAP, CERM, 10 pF, 25 V,+/- 5%, C0G/NP0, 0201; Manufacturer: MuRata; Polarized: N; CompType: Capacitor; Value: 10pF; U/M: EA; Cap_F: 0.00000000001; Tolerance_%: 5; VDC_V: 25; Value2: 25V; TaMin_C: -55; TaMax_C: 125; Cap_Case: 0201; SizeArea_mm2: 0.18; SizeAreaWB_mm2: 2.08; SizeX_mm: 0.6; SizeY_mm: 0.3; SizeZ_mm: 0.26; AEC Category: Q200
signal-integrity model Cap
simulation model Cap
footprint 0201
footprint 0201M
footprint 0201L
footprint 0201_Silk
pins: 1, 2

## GJM1555C1H1R0BB01D
designator C?  ValueDisplayed: 1pF  (hidden comment: GJM1555C1H1R0BB01D)
CAP, CERM, 1 pF, 50 V,+/- 10%, C0G/NP0, 0402; Manufacturer: MuRata; Polarized: N; CompType: Capacitor; Value: 1pF; U/M: EA; Cap_F: 0.000000000001; Tolerance_%: 10; VDC_V: 50; Value2: 50V; TaMin_C: -55; TaMax_C: 125; Cap_Case: 0402; SizeArea_mm2: 0.5; SizeAreaWB_mm2: 3; SizeX_mm: 1; SizeZ_mm: 0.6; AEC Category: Q200
signal-integrity model Cap
simulation model Cap
footprint 0402
footprint 0402M
footprint 0402L
footprint 0402S
pins: 1, 2

## GJM1555C1H1R1WB01D
designator C?  ValueDisplayed: 1.1pF  (hidden comment: GJM1555C1H1R1WB01D)
CAP, CERM, 1.1 pF, 50 V,+/- 5%, C0G/NP0, 0402; Manufacturer: MuRata; Polarized: N; CompType: Capacitor; Value: 1.1pF; U/M: EA; Cap_F: 0.0000000000011; Tolerance_%: 5; VDC_V: 50; Value2: 50V; TaMin_C: -55; TaMax_C: 125; Cap_Case: 0402; SizeArea_mm2: 0.5; SizeAreaWB_mm2: 3; SizeX_mm: 1; SizeZ_mm: 0.6; AEC Category: Q200
signal-integrity model Cap
simulation model Cap
footprint 0402
footprint 0402M
footprint 0402L
footprint 0402S
pins: 1, 2

## GJM1555C1H1R3CB01D
designator C?  ValueDisplayed: 1.3pF  (hidden comment: GJM1555C1H1R3CB01D)
CAP, CERM, 1.3 pF, 50 V,+/- 20%, C0G/NP0, 0402; Manufacturer: MuRata; Polarized: N; CompType: Capacitor; Value: 1.3pF; U/M: EA; Cap_F: 0.0000000000013; Tolerance_%: 20; VDC_V: 50; Value2: 50V; TaMin_C: -55; TaMax_C: 125; Cap_Case: 0402; SizeArea_mm2: 0.5; SizeAreaWB_mm2: 3; SizeX_mm: 1; SizeZ_mm: 0.6; AEC Category: Q200
signal-integrity model Cap
simulation model Cap
footprint 0402
footprint 0402M
footprint 0402L
footprint 0402S
pins: 1, 2

## GJM1555C1H2R0CB01D
designator C?  ValueDisplayed: 2pF  (hidden comment: GJM1555C1H2R0CB01D)
CAP, CERM, 2 pF, 50 V,+/- 15%, C0G/NP0, 0402; Manufacturer: MuRata; Polarized: N; CompType: Capacitor; Value: 2pF; U/M: EA; Cap_F: 0.000000000002; Tolerance_%: 15; VDC_V: 50; Value2: 50V; TaMin_C: -55; TaMax_C: 125; Cap_Case: 0402; SizeArea_mm2: 0.5; SizeAreaWB_mm2: 3; SizeX_mm: 1; SizeZ_mm: 0.6; AEC Category: Q200
signal-integrity model Cap
simulation model Cap
footprint 0402
footprint 0402M
footprint 0402L
footprint 0402S
pins: 1, 2

## GJM1555C1H4R7BB01D
designator C?  ValueDisplayed: 4.7pF  (hidden comment: GJM1555C1H4R7BB01D)
CAP, CERM, 4.7 pF, 50 V,+/- 2%, C0G/NP0, 0402; Manufacturer: MuRata; Polarized: N; CompType: Capacitor; Value: 4.7pF; U/M: EA; Cap_F: 0.0000000000047; Tolerance_%: 2; VDC_V: 50; Value2: 50V; TaMin_C: -55; TaMax_C: 125; Cap_Case: 0402; SizeArea_mm2: 0.5; SizeAreaWB_mm2: 3; SizeX_mm: 1; SizeZ_mm: 0.6; AEC Category: Q200; Green_Lifecycle: Active; Green_REACh: Passed
signal-integrity model Cap
simulation model Cap
footprint 0402
footprint 0402M
footprint 0402L
footprint 0402S
pins: 1, 2

## GJM1555C1H270JB01
designator C?  ValueDisplayed: 27pF  (hidden comment: GJM1555C1H270JB01)
CAP, CERM, 27 pF, 50 V,+/- 5%, C0G/NP0, 0402; Manufacturer: MuRata; Polarized: N; CompType: Capacitor; Value: 27pF; U/M: EA; Cap_F: 0.000000000027; Tolerance_%: 5; VDC_V: 50; Value2: 50V; TaMin_C: -55; TaMax_C: 125; Cap_Case: 0402; SizeArea_mm2: 0.5; SizeAreaWB_mm2: 3; SizeX_mm: 1; SizeZ_mm: 0.6; AEC Category: Q200
signal-integrity model Cap
simulation model Cap
footprint 0402
footprint 0402M
footprint 0402L
footprint 0402S
pins: 1, 2

## GJM1555C1HR40BB01D
designator C?  ValueDisplayed: 0.4pF  (hidden comment: GJM1555C1HR40BB01D)
CAP, CERM, 0.4 pF, 50 V,+/- 25%, C0G/NP0, 0402; Manufacturer: MuRata; Polarized: N; CompType: Capacitor; Value: 0.4pF; U/M: EA; Cap_F: 0.0000000000004; Tolerance_%: 25; VDC_V: 50; Value2: 50V; TaMin_C: -55; TaMax_C: 125; Cap_Case: 0402; SizeArea_mm2: 0.5; SizeAreaWB_mm2: 3; SizeX_mm: 1; SizeZ_mm: 0.6; AEC Category: Q200
signal-integrity model Cap
simulation model Cap
footprint 0402
footprint 0402M
footprint 0402L
footprint 0402S
pins: 1, 2

## GJM1555C1HR60BB01D
designator C?  ValueDisplayed: 0.6pF  (hidden comment: GJM1555C1HR60BB01D)
CAP, CERM, 0.6pF, 50 V,+/- 18%, C0G/NP0, 0402; Manufacturer: MuRata; Polarized: N; CompType: Capacitor; U/M: EA; Cap_F: 0.0000000000006; Tolerance_%: 18; VDC_V: 50; Value2: 50V; TaMin_C: -55; TaMax_C: 125; Cap_Case: 0402; SizeArea_mm2: 0.5; SizeAreaWB_mm2: 3; SizeX_mm: 1; SizeZ_mm: 0.6; AEC Category: Q200; Green_Lifecycle: Active; Green_REACh: Passed
signal-integrity model Cap
simulation model Cap
footprint 0402
footprint 0402M
footprint 0402L
footprint 0402S
pins: 1, 2

## GMK105BJ104KV-F
designator C?  ValueDisplayed: 0.1µF  (hidden comment: GMK105BJ104KV-F)
CAP, CERM, 0.1 µF, 35 V,+/- 10%, X5R, 0402; Manufacturer: Taiyo Yuden; Polarized: N; CompType: Capacitor; Value: 0.1uF; U/M: EA; Cap_F: 0.0000001; Tolerance_%: 10; VDC_V: 35; Value2: 35V; TaMin_C: -55; TaMax_C: 85; Cap_Case: 0402; SizeArea_mm2: 0.5; SizeAreaWB_mm2: 3; SizeX_mm: 1; SizeZ_mm: 0.6; AEC Category: Q200; Green_Lifecycle: Active; Green_REACh: Passed
signal-integrity model Cap
simulation model Cap
footprint 0402
footprint 0402M
footprint 0402L
footprint 0402S
pins: 1, 2

## GMK107AB7105KAHT
designator C?  ValueDisplayed: 1µF  (hidden comment: GMK107AB7105KAHT)
CAP, CERM, 1 µF, 35 V,+/- 10%, X7R, AEC-Q200 Grade 0, 0603; Manufacturer: Taiyo Yuden; Polarized: N; CompType: Capacitor; Value: 1uF; U/M: EA; Cap_F: 0.000001; Tolerance_%: 10; VDC_V: 35; Value2: 35V; TaMin_C: -55; TaMax_C: 125; Cap_Case: 0603; SizeArea_mm2: 1.28; SizeAreaWB_mm2: 4.68; SizeX_mm: 1.6; SizeY_mm: 0.8; SizeZ_mm: 1; AEC Category: Q200; AEC Qualified: Y; AEC Grade: 0
signal-integrity model Cap
simulation model Cap
footprint 0603
footprint 0603M
footprint 0603L
footprint 0603_HV
footprint 0603S
pins: 1, 2

## GMK107BJ105KA-T
designator C?  ValueDisplayed: 1µF  (hidden comment: GMK107BJ105KA-T)
CAP, CERM, 1 µF, 35 V,+/- 10%, X5R, 0603; Manufacturer: Taiyo Yuden; Polarized: N; CompType: Capacitor; Value: 1uF; U/M: EA; Cap_F: 0.000001; Tolerance_%: 10; VDC_V: 35; Value2: 35V; TaMin_C: -55; TaMax_C: 85; Cap_Case: 0603; SizeArea_mm2: 1.28; SizeAreaWB_mm2: 4.68; SizeX_mm: 1.6; SizeY_mm: 0.8; SizeZ_mm: 1; AEC Category: Q200; Green_Lifecycle: Active; Green_REACh: Passed
signal-integrity model Cap
simulation model Cap
footprint 0603
footprint 0603M
footprint 0603L
footprint 0603_HV
footprint 0603S
pins: 1, 2

## GMK212B7105KG-T
designator C?  ValueDisplayed: 1µF  (hidden comment: GMK212B7105KG-T)
CAP, CERM, 1 µF, 35 V,+/- 10%, X7R, 0805; Manufacturer: Taiyo Yuden; Polarized: N; CompType: Capacitor; Value: 1uF; U/M: EA; Cap_F: 0.000001; Tolerance_%: 10; VDC_V: 35; Value2: 35V; TaMin_C: -55; TaMax_C: 125; Cap_Case: 0805; SizeArea_mm2: 2.5; SizeAreaWB_mm2: 6.75; SizeX_mm: 2; SizeY_mm: 1.25; SizeZ_mm: 1.45; AEC Category: Q200; Green_Lifecycle: Active; Green_REACh: Passed
signal-integrity model Cap
simulation model Cap
footprint 0805_HV
footprint 0805_HV1
footprint 0805
footprint 0805M
footprint 0805L
pins: 1, 2

## GMK212BJ474KG-T
designator C?  ValueDisplayed: 0.47µF  (hidden comment: GMK212BJ474KG-T)
CAP, CERM, 0.47 µF, 35 V,+/- 10%, X5R, 0805; Manufacturer: Taiyo Yuden; Polarized: N; CompType: Capacitor; Value: 0.47uF; U/M: EA; Cap_F: 0.00000047; Tolerance_%: 10; VDC_V: 35; Value2: 35V; TaMin_C: -55; TaMax_C: 85; Cap_Case: 0805; SizeArea_mm2: 2.5; SizeAreaWB_mm2: 6.75; SizeX_mm: 2; SizeY_mm: 1.25; SizeZ_mm: 1.45; AEC Category: Q200; Green_Lifecycle: Not Set; Green_REACh: Incomplete
signal-integrity model Cap
simulation model Cap
footprint 0805_HV
footprint 0805_HV1
footprint 0805
footprint 0805M
footprint 0805L
pins: 1, 2

## GMK316AB7106KL
designator C?  ValueDisplayed: 10µF  (hidden comment: GMK316AB7106KL)
CAP, CERM, 10 µF, 35 V,+/- 10%, X7R, 1206; Manufacturer: Taiyo Yuden; Polarized: N; CompType: Capacitor; Value: 10uF; U/M: EA; Cap_F: 0.00001; Tolerance_%: 10; VDC_V: 35; Value2: 35V; TaMin_C: -55; TaMax_C: 125; Cap_Case: 1206; SizeArea_mm2: 5.12; SizeAreaWB_mm2: 10.92; SizeX_mm: 3.2; SizeY_mm: 1.6; SizeZ_mm: 1.35; AEC Category: Q200; Green_Lifecycle: Active; Green_REACh: Passed
signal-integrity model Cap
simulation model Cap
footprint 1206
footprint 1206M
footprint 1206L
pins: 1, 2

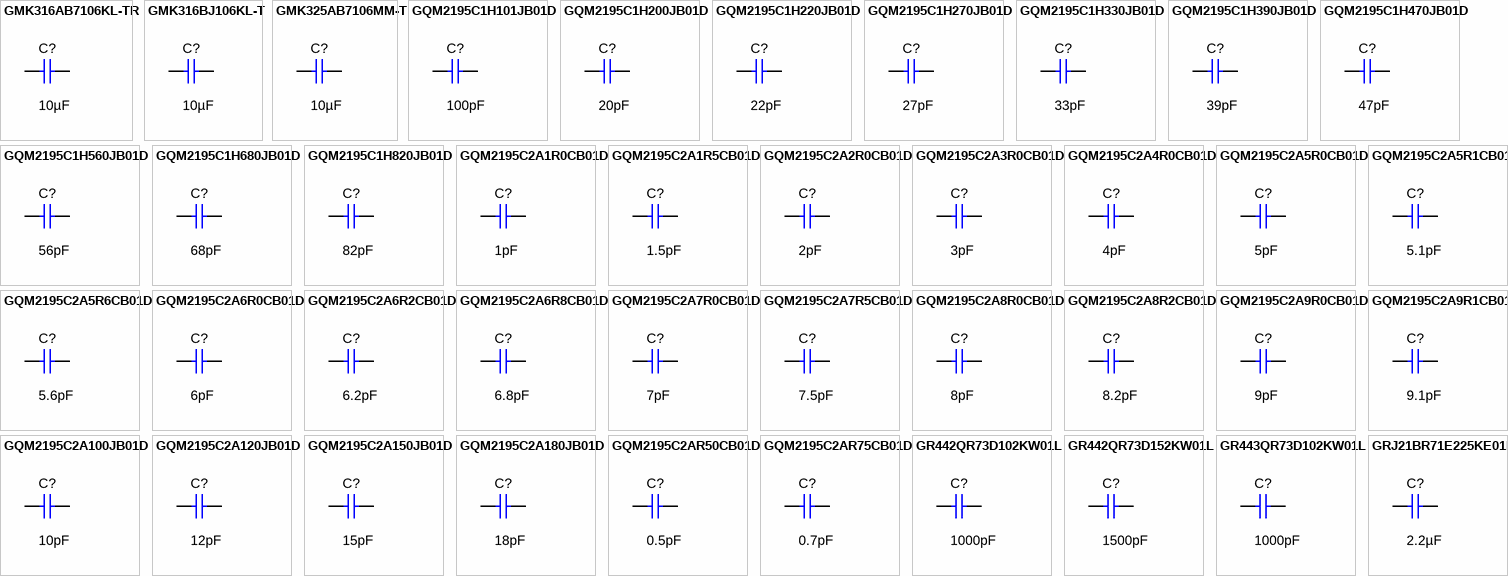
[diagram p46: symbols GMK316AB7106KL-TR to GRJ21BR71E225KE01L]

## GMK316AB7106KL-TR
designator C?  ValueDisplayed: 10µF  (hidden comment: GMK316AB7106KL-TR)
CAP, CERM, 10 µF, 35 V,+/- 10%, X7R, 1206; Manufacturer: Taiyo Yuden; Polarized: N; CompType: Capacitor; Value: 10uF; U/M: EA; Cap_F: 0.00001; Tolerance_%: 10; VDC_V: 35; Value2: 35V; TaMin_C: -55; TaMax_C: 125; Cap_Case: 1206; SizeArea_mm2: 5.12; SizeAreaWB_mm2: 10.92; SizeX_mm: 3.2; SizeY_mm: 1.6; SizeZ_mm: 1.9; AEC Category: Q200; Green_Lifecycle: Active; Green_REACh: Passed
signal-integrity model Cap
simulation model Cap
footprint 1206_190
footprint 1206_190M
footprint 1206_190L
pins: 1, 2

## GMK316BJ106KL-T
designator C?  ValueDisplayed: 10µF  (hidden comment: GMK316BJ106KL-T)
CAP, CERM, 10 µF, 35 V,+/- 10%, X5R, 1206; Manufacturer: Taiyo Yuden; Polarized: N; CompType: Capacitor; Value: 10uF; U/M: EA; Cap_F: 0.00001; Tolerance_%: 10; VDC_V: 35; Value2: 35V; TaMin_C: -55; TaMax_C: 85; Cap_Case: 1206; SizeArea_mm2: 5.12; SizeAreaWB_mm2: 10.92; SizeX_mm: 3.2; SizeY_mm: 1.6; SizeZ_mm: 1.9; AEC Category: Q200; Green_Lifecycle: Not Set; Green_REACh: Incomplete
signal-integrity model Cap
simulation model Cap
footprint 1206_190
footprint 1206_190M
footprint 1206_190L
pins: 1, 2

## GMK325AB7106MM-T
designator C?  ValueDisplayed: 10µF  (hidden comment: GMK325AB7106MM-T)
CAP, CERM, 10 µF, 35 V,+/- 20%, X7R, 1210; Manufacturer: Taiyo Yuden; Polarized: N; CompType: Capacitor; Value: 10uF; U/M: EA; Cap_F: 0.00001; Tolerance_%: 20; VDC_V: 35; Value2: 35V; TaMin_C: -55; TaMax_C: 125; Cap_Case: 1210; SizeArea_mm2: 8; SizeAreaWB_mm2: 14.7; SizeX_mm: 3.2; SizeY_mm: 2.5; SizeZ_mm: 1.35; AEC Category: Q200; Green_Lifecycle: Not Set; Green_REACh: Incomplete
signal-integrity model Cap
simulation model Cap
footprint 1210
footprint 1210M
footprint 1210L
pins: 1, 2

## GQM2195C1H101JB01D
designator C?  ValueDisplayed: 100pF  (hidden comment: GQM2195C1H101JB01D)
CAP, CERM, 100 pF, 50 V,+/- 5%, C0G/NP0, 0805; Manufacturer: MuRata; Polarized: N; CompType: Capacitor; Value: 100pF; U/M: EA; Cap_F: 0.0000000001; Tolerance_%: 5; VDC_V: 50; Value2: 50V; TaMin_C: -55; TaMax_C: 125; Cap_Case: 0805; SizeArea_mm2: 2.5; SizeAreaWB_mm2: 6.75; SizeX_mm: 2; SizeY_mm: 1.25; SizeZ_mm: 1.45; AEC Category: Q200
signal-integrity model Cap
simulation model Cap
footprint 0805_HV
footprint 0805_HV1
footprint 0805
footprint 0805M
footprint 0805L
pins: 1, 2

## GQM2195C1H200JB01D
designator C?  ValueDisplayed: 20pF  (hidden comment: GQM2195C1H200JB01D)
CAP, CERM, 20 pF, 50 V,+/- 5%, C0G/NP0, 0805; Manufacturer: MuRata; Polarized: N; CompType: Capacitor; Value: 20pF; U/M: EA; Cap_F: 0.00000000002; Tolerance_%: 5; VDC_V: 50; Value2: 50V; TaMin_C: -55; TaMax_C: 125; Cap_Case: 0805; SizeArea_mm2: 2.5; SizeAreaWB_mm2: 6.75; SizeX_mm: 2; SizeY_mm: 1.25; SizeZ_mm: 1.45; AEC Category: Q200
signal-integrity model Cap
simulation model Cap
footprint 0805_HV
footprint 0805_HV1
footprint 0805
footprint 0805M
footprint 0805L
pins: 1, 2

## GQM2195C1H220JB01D
designator C?  ValueDisplayed: 22pF  (hidden comment: GQM2195C1H220JB01D)
CAP, CERM, 22 pF, 50 V,+/- 5%, C0G/NP0, 0805; Manufacturer: MuRata; Polarized: N; CompType: Capacitor; Value: 22pF; U/M: EA; Cap_F: 0.000000000022; Tolerance_%: 5; VDC_V: 50; Value2: 50V; TaMin_C: -55; TaMax_C: 125; Cap_Case: 0805; SizeArea_mm2: 2.5; SizeAreaWB_mm2: 6.75; SizeX_mm: 2; SizeY_mm: 1.25; SizeZ_mm: 1.45; AEC Category: Q200
signal-integrity model Cap
simulation model Cap
footprint 0805_HV
footprint 0805_HV1
footprint 0805
footprint 0805M
footprint 0805L
pins: 1, 2

## GQM2195C1H270JB01D
designator C?  ValueDisplayed: 27pF  (hidden comment: GQM2195C1H270JB01D)
CAP, CERM, 27 pF, 50 V,+/- 5%, C0G/NP0, 0805; Manufacturer: MuRata; Polarized: N; CompType: Capacitor; Value: 27pF; U/M: EA; Cap_F: 0.000000000027; Tolerance_%: 5; VDC_V: 50; Value2: 50V; TaMin_C: -55; TaMax_C: 125; Cap_Case: 0805; SizeArea_mm2: 2.5; SizeAreaWB_mm2: 6.75; SizeX_mm: 2; SizeY_mm: 1.25; SizeZ_mm: 1.45; AEC Category: Q200; Green_Lifecycle: Not Set; Green_REACh: Incomplete
signal-integrity model Cap
simulation model Cap
footprint 0805_HV
footprint 0805_HV1
footprint 0805
footprint 0805M
footprint 0805L
pins: 1, 2

## GQM2195C1H330JB01D
designator C?  ValueDisplayed: 33pF  (hidden comment: GQM2195C1H330JB01D)
CAP, CERM, 33 pF, 50 V,+/- 5%, C0G/NP0, 0805; Manufacturer: MuRata; Polarized: N; CompType: Capacitor; Value: 33pF; U/M: EA; Cap_F: 0.000000000033; Tolerance_%: 5; VDC_V: 50; Value2: 50V; TaMin_C: -55; TaMax_C: 125; Cap_Case: 0805; SizeArea_mm2: 2.5; SizeAreaWB_mm2: 6.75; SizeX_mm: 2; SizeY_mm: 1.25; SizeZ_mm: 1.45; AEC Category: Q200
signal-integrity model Cap
simulation model Cap
footprint 0805_HV
footprint 0805_HV1
footprint 0805
footprint 0805M
footprint 0805L
pins: 1, 2

## GQM2195C1H390JB01D
designator C?  ValueDisplayed: 39pF  (hidden comment: GQM2195C1H390JB01D)
CAP, CERM, 39 pF, 50 V,+/- 5%, C0G/NP0, 0805; Manufacturer: MuRata; Polarized: N; CompType: Capacitor; Value: 39pF; U/M: EA; Cap_F: 0.000000000039; Tolerance_%: 5; VDC_V: 50; Value2: 50V; TaMin_C: -55; TaMax_C: 125; Cap_Case: 0805; SizeArea_mm2: 2.5; SizeAreaWB_mm2: 6.75; SizeX_mm: 2; SizeY_mm: 1.25; SizeZ_mm: 1.45; AEC Category: Q200
signal-integrity model Cap
simulation model Cap
footprint 0805_HV
footprint 0805_HV1
footprint 0805
footprint 0805M
footprint 0805L
pins: 1, 2

## GQM2195C1H470JB01D
designator C?  ValueDisplayed: 47pF  (hidden comment: GQM2195C1H470JB01D)
CAP, CERM, 47 pF, 50 V,+/- 5%, C0G/NP0, 0805; Manufacturer: MuRata; Polarized: N; CompType: Capacitor; Value: 47pF; U/M: EA; Cap_F: 0.000000000047; Tolerance_%: 5; VDC_V: 50; Value2: 50V; TaMin_C: -55; TaMax_C: 125; Cap_Case: 0805; SizeArea_mm2: 2.5; SizeAreaWB_mm2: 6.75; SizeX_mm: 2; SizeY_mm: 1.25; SizeZ_mm: 1.45; AEC Category: Q200
signal-integrity model Cap
simulation model Cap
footprint 0805_HV
footprint 0805_HV1
footprint 0805
footprint 0805M
footprint 0805L
pins: 1, 2

## GQM2195C1H560JB01D
designator C?  ValueDisplayed: 56pF  (hidden comment: GQM2195C1H560JB01D)
CAP, CERM, 56 pF, 50 V,+/- 5%, C0G/NP0, 0805; Manufacturer: MuRata; Polarized: N; CompType: Capacitor; Value: 56pF; U/M: EA; Cap_F: 0.000000000056; Tolerance_%: 5; VDC_V: 50; Value2: 50V; TaMin_C: -55; TaMax_C: 125; Cap_Case: 0805; SizeArea_mm2: 2.5; SizeAreaWB_mm2: 6.75; SizeX_mm: 2; SizeY_mm: 1.25; SizeZ_mm: 1.45; AEC Category: Q200
signal-integrity model Cap
simulation model Cap
footprint 0805_HV
footprint 0805_HV1
footprint 0805
footprint 0805M
footprint 0805L
pins: 1, 2

## GQM2195C1H680JB01D
designator C?  ValueDisplayed: 68pF  (hidden comment: GQM2195C1H680JB01D)
CAP, CERM, 68 pF, 50 V,+/- 5%, C0G/NP0, 0805; Manufacturer: MuRata; Polarized: N; CompType: Capacitor; Value: 68pF; U/M: EA; Cap_F: 0.000000000068; Tolerance_%: 5; VDC_V: 50; Value2: 50V; TaMin_C: -55; TaMax_C: 125; Cap_Case: 0805; SizeArea_mm2: 2.5; SizeAreaWB_mm2: 6.75; SizeX_mm: 2; SizeY_mm: 1.25; SizeZ_mm: 1.45; AEC Category: Q200; Green_Lifecycle: Not Set; Green_REACh: Incomplete
signal-integrity model Cap
simulation model Cap
footprint 0805_HV
footprint 0805_HV1
footprint 0805
footprint 0805M
footprint 0805L
pins: 1, 2

## GQM2195C1H820JB01D
designator C?  ValueDisplayed: 82pF  (hidden comment: GQM2195C1H820JB01D)
CAP, CERM, 82 pF, 50 V,+/- 5%, C0G/NP0, 0805; Manufacturer: MuRata; Polarized: N; CompType: Capacitor; Value: 82pF; U/M: EA; Cap_F: 0.000000000082; Tolerance_%: 5; VDC_V: 50; Value2: 50V; TaMin_C: -55; TaMax_C: 125; Cap_Case: 0805; SizeArea_mm2: 2.5; SizeAreaWB_mm2: 6.75; SizeX_mm: 2; SizeY_mm: 1.25; SizeZ_mm: 1.45; AEC Category: Q200
signal-integrity model Cap
simulation model Cap
footprint 0805_HV
footprint 0805_HV1
footprint 0805
footprint 0805M
footprint 0805L
pins: 1, 2

## GQM2195C2A1R0CB01D
designator C?  ValueDisplayed: 1pF  (hidden comment: GQM2195C2A1R0CB01D)
CAP, CERM, 1 pF, 100 V,+/- 5%, C0G/NP0, 0805; Manufacturer: MuRata; Polarized: N; CompType: Capacitor; Value: 1pF; U/M: EA; Cap_F: 0.000000000001; Tolerance_%: 5; VDC_V: 100; Value2: 100V; TaMin_C: -55; TaMax_C: 125; Cap_Case: 0805; SizeArea_mm2: 2.5; SizeAreaWB_mm2: 6.75; SizeX_mm: 2; SizeY_mm: 1.25; SizeZ_mm: 1.45; AEC Category: Q200
signal-integrity model Cap
simulation model Cap
footprint 0805_HV
footprint 0805_HV1
footprint 0805
footprint 0805M
footprint 0805L
pins: 1, 2

## GQM2195C2A1R5CB01D
designator C?  ValueDisplayed: 1.5pF  (hidden comment: GQM2195C2A1R5CB01D)
CAP, CERM, 1.5 pF, 100 V,+/- 5%, C0G/NP0, 0805; Manufacturer: MuRata; Polarized: N; CompType: Capacitor; Value: 1.5pF; U/M: EA; Cap_F: 0.0000000000015; Tolerance_%: 5; VDC_V: 100; Value2: 100V; TaMin_C: -55; TaMax_C: 125; Cap_Case: 0805; SizeArea_mm2: 2.5; SizeAreaWB_mm2: 6.75; SizeX_mm: 2; SizeY_mm: 1.25; SizeZ_mm: 1.45; AEC Category: Q200
signal-integrity model Cap
simulation model Cap
footprint 0805_HV
footprint 0805_HV1
footprint 0805
footprint 0805M
footprint 0805L
pins: 1, 2

## GQM2195C2A2R0CB01D
designator C?  ValueDisplayed: 2pF  (hidden comment: GQM2195C2A2R0CB01D)
CAP, CERM, 2 pF, 100 V,+/- 5%, C0G/NP0, 0805; Manufacturer: MuRata; Polarized: N; CompType: Capacitor; Value: 2pF; U/M: EA; Cap_F: 0.000000000002; Tolerance_%: 5; VDC_V: 100; Value2: 100V; TaMin_C: -55; TaMax_C: 125; Cap_Case: 0805; SizeArea_mm2: 2.5; SizeAreaWB_mm2: 6.75; SizeX_mm: 2; SizeY_mm: 1.25; SizeZ_mm: 1.45; AEC Category: Q200
signal-integrity model Cap
simulation model Cap
footprint 0805_HV
footprint 0805_HV1
footprint 0805
footprint 0805M
footprint 0805L
pins: 1, 2

## GQM2195C2A3R0CB01D
designator C?  ValueDisplayed: 3pF  (hidden comment: GQM2195C2A3R0CB01D)
CAP, CERM, 3 pF, 100 V,+/- 5%, C0G/NP0, 0805; Manufacturer: MuRata; Polarized: N; CompType: Capacitor; Value: 3pF; U/M: EA; Cap_F: 0.000000000003; Tolerance_%: 5; VDC_V: 100; Value2: 100V; TaMin_C: -55; TaMax_C: 125; Cap_Case: 0805; SizeArea_mm2: 2.5; SizeAreaWB_mm2: 6.75; SizeX_mm: 2; SizeY_mm: 1.25; SizeZ_mm: 1.45; AEC Category: Q200
signal-integrity model Cap
simulation model Cap
footprint 0805_HV
footprint 0805_HV1
footprint 0805
footprint 0805M
footprint 0805L
pins: 1, 2

## GQM2195C2A4R0CB01D
designator C?  ValueDisplayed: 4pF  (hidden comment: GQM2195C2A4R0CB01D)
CAP, CERM, 4 pF, 100 V,+/- 5%, C0G/NP0, 0805; Manufacturer: MuRata; Polarized: N; CompType: Capacitor; Value: 4pF; U/M: EA; Cap_F: 0.000000000004; Tolerance_%: 5; VDC_V: 100; Value2: 100V; TaMin_C: -55; TaMax_C: 125; Cap_Case: 0805; SizeArea_mm2: 2.5; SizeAreaWB_mm2: 6.75; SizeX_mm: 2; SizeY_mm: 1.25; SizeZ_mm: 1.45; AEC Category: Q200
signal-integrity model Cap
simulation model Cap
footprint 0805_HV
footprint 0805_HV1
footprint 0805
footprint 0805M
footprint 0805L
pins: 1, 2

## GQM2195C2A5R0CB01D
designator C?  ValueDisplayed: 5pF  (hidden comment: GQM2195C2A5R0CB01D)
CAP, CERM, 5 pF, 100 V,+/- 5%, C0G/NP0, 0805; Manufacturer: MuRata; Polarized: N; CompType: Capacitor; Value: 5pF; U/M: EA; Cap_F: 0.000000000005; Tolerance_%: 5; VDC_V: 100; Value2: 100V; TaMin_C: -55; TaMax_C: 125; Cap_Case: 0805; SizeArea_mm2: 2.5; SizeAreaWB_mm2: 6.75; SizeX_mm: 2; SizeY_mm: 1.25; SizeZ_mm: 1.45; AEC Category: Q200
signal-integrity model Cap
simulation model Cap
footprint 0805_HV
footprint 0805_HV1
footprint 0805
footprint 0805M
footprint 0805L
pins: 1, 2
